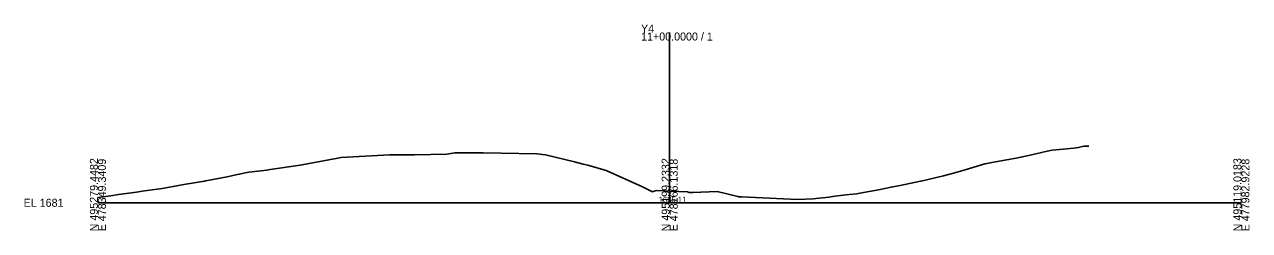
# Model space of a CAD drawing. Extents: x -26 to 403, y -10 to 5108.
# Drawn here: x -25.7 to 402.8, y 990.3 to 1062.3 of the extents above; entities that cross this region are included whole.
import ezdxf

# ---------------------------------------------------------------- set-up
doc = ezdxf.new("R2010")
doc.units = 0
for name, color, linetype in [('Exist Cross Section Cell', 7, 'Continuous'), ('Exist XS Center Line Elevation Label', 7, 'Continuous'), ('Exist XS Ground Line', 7, 'Continuous')]:
    doc.layers.add(name, color=color, linetype=linetype)

msp = doc.modelspace()

# ---------------------------------------------------------------- linework, layer by layer
at = {"layer": 'Exist Cross Section Cell'}
for p, q in [((200, 1000), (200, 1059.54)), ((0, 1000), (200, 1000)), ((200, 1000), (400, 1000))]:
    msp.add_line(p, q, dxfattribs=at)
at = {"layer": 'Exist XS Ground Line'}
msp.add_lwpolyline([(0, 1001.81), (4.52, 1002.45), (7.24, 1002.92), (13.44, 1003.72), (14.83, 1003.92), (15.44, 1004.01), (22.42, 1005.04), (26.36, 1005.71), (30.02, 1006.35), (37.28, 1007.6), (37.61, 1007.67), (38.38, 1007.8), (45.2, 1009.1), (48.19, 1009.75), (52.8, 1010.72), (59.11, 1011.44), (60.23, 1011.61), (70.72, 1013.2), (83.97, 1015.59), (84.47, 1015.67), (84.94, 1015.78), (87.15, 1015.89), (102.04, 1016.71), (104.22, 1016.75), (105.68, 1016.75), (110.7, 1016.74), (122.04, 1016.96), (124.85, 1017.41), (134.78, 1017.47), (153.5, 1017.13), (156.61, 1016.8), (166.67, 1014.31), (169.69, 1013.54), (171.36, 1013.11), (177.77, 1011.24), (190.3, 1005.7), (193.95, 1003.87), (194.57, 1004.1), (195.43, 1004.31), (200.14, 1004.1), (206.24, 1003.86), (206.87, 1003.57), (208.05, 1003.65), (216.56, 1003.97), (223.82, 1002.15), (224.22, 1002.07), (225.17, 1002.03), (244.73, 1001.14), (250.24, 1001.39), (255.65, 1002.01), (257.83, 1002.27), (262.82, 1002.84), (265.42, 1003.17), (266.57, 1003.36), (273.02, 1004.55), (277.48, 1005.46), (280.61, 1006.08), (287.75, 1007.55), (288.4, 1007.7), (295.8, 1009.46), (299.32, 1010.39), (303.39, 1011.49), (310.24, 1013.6), (310.99, 1013.78), (312.69, 1014.08), (318.58, 1015.12), (321.16, 1015.61), (326.17, 1016.69), (332.08, 1018.04), (333.77, 1018.36), (337.63, 1018.74), (341.36, 1019.12), (343, 1019.32), (344.93, 1019.75), (346.58, 1019.85)], dxfattribs=at)

# ---------------------------------------------------------------- texts
at = {"layer": 'Exist Cross Section Cell'}
for s, p in [('Y4', (190, 1059.54)), ('11+00.0000 / 1', (190, 1056.74)), ('EL 1681', (-26, 998.6))]:
    msp.add_text(s, height=2.8, dxfattribs=at).set_placement(p)
for s, p in [('N 495279.4482', (0, 990)), ('E 478349.3409', (2.8, 990)), ('N 495199.2332', (200, 990)), ('E 478166.1318', (202.8, 990)), ('N 495119.0183', (400, 990)), ('E 477982.9228', (402.8, 990))]:
    msp.add_text(s, height=2.8, rotation=90, dxfattribs=at).set_placement(p)
at = {"layer": 'Exist XS Center Line Elevation Label'}
msp.add_text('1685.11', height=2, dxfattribs=at).set_placement((196.17, 1000.11))

doc.saveas('drawing.dxf')
